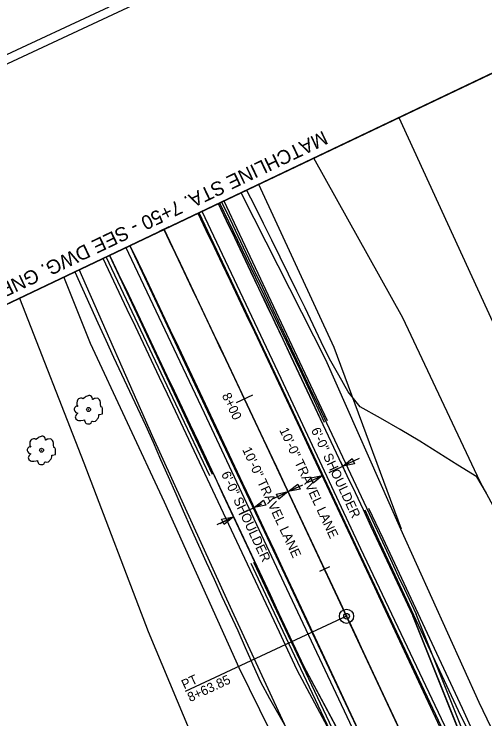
# Model space of a CAD drawing. Extents: x 1040567 to 1041254, y 1126791 to 1127594.
# Drawn here: x 1040797.5 to 1040922.7, y 1127312.2 to 1127499.7 of the extents above; entities that cross this region are included whole.
import ezdxf

# ---------------------------------------------------------------- set-up
doc = ezdxf.new("R2010")
doc.units = 0
for name, color, linetype in [('AC_P', 7, 'Continuous'), ('ACP_P', 7, 'Continuous'), ('ACSC_P_T', 7, 'Continuous'), ('ACSCT_P', 7, 'Continuous'), ('ACSR_P_T', 7, 'Continuous'), ('ACSRT_P', 7, 'Continuous'), ('clip boundary', 7, 'Continuous'), ('LELB', 7, 'Continuous'), ('LFILL_P', 7, 'Continuous'), ('LTD', 7, 'Continuous'), ('NML_P', 7, 'Continuous'), ('NML_P_T', 7, 'Continuous'), ('O_Details_Dimensions_Extension_Lines_P', 7, 'Continuous'), ('PE', 7, 'Continuous'), ('PE_P', 7, 'Continuous'), ('PET_P', 7, 'Continuous'), ('RBS_P', 7, 'Continuous'), ('RDU', 7, 'Continuous'), ('RGB_P', 7, 'Continuous'), ('RGC', 7, 'Continuous'), ('SHEET_BORDER', 7, 'Continuous'), ('STFBY', 7, 'Continuous'), ('STFBY_P', 7, 'Continuous'), ('STSEW', 7, 'Continuous'), ('UEO', 7, 'Continuous')]:
    doc.layers.add(name, color=color, linetype=linetype)

msp = doc.modelspace()

# ---------------------------------------------------------------- linework, layer by layer
at = {"layer": 'AC_P'}
msp.add_line((1040885.87, 1127339.47), (1041008.87, 1127076.16), dxfattribs=at)
msp.add_arc((1027295.55, 1120991.01), 15000, 25.038741, 25.473615, dxfattribs=at)
at = {"layer": 'ACP_P'}
for radius in [1.89, 0.744, 0.154]:
    msp.add_circle((1040885.87, 1127339.47), radius, dxfattribs=at)
at = {"layer": 'ACSCT_P'}
msp.add_lwpolyline([(1040885.87, 1127339.47), (1040842.95, 1127319.43)], dxfattribs=at)
at = {"layer": 'ACSRT_P'}
for points in [[(1040838.6, 1127443.06), (1040836, 1127441.82)], [(1040860.9, 1127398.29), (1040856.56, 1127396.24)], [(1040881.31, 1127352.63), (1040878.7, 1127351.41)]]:
    msp.add_lwpolyline(points, dxfattribs=at)
at = {"layer": 'clip boundary'}
msp.add_lwpolyline([(1040984.84, 1127512.73), (1041214.88, 1127013.05), (1040933.62, 1126879.17), (1040829.04, 1127018.95), (1040710.75, 1127268.88), (1040738.34, 1127281.77), (1040695.57, 1127374.92)], close=True, dxfattribs=at)
at = {"layer": 'LELB'}
for points in [[(1040877.08, 1127461.4), (1040900.78, 1127418.95), (1040921.32, 1127375.3), (1040945.34, 1127330.9), (1040968.92, 1127282.31)], [(1040862.49, 1127454.44), (1040882.5, 1127411.03), (1040900.36, 1127362.7)], [(1040936.75, 1127274.21), (1040940.48, 1127276.28), (1040921.13, 1127316.56), (1040900.31, 1127362.66), (1040880.33, 1127407.66), (1040858.09, 1127451.64), (1040857.81, 1127452.21)], [(1040895.94, 1127263.89), (1040885.7, 1127276.54), (1040878.39, 1127291.15), (1040855.44, 1127340.92), (1040834.33, 1127387.23), (1040814.73, 1127431.69)], [(1040900.67, 1127263.1), (1040889.71, 1127266.18), (1040883.77, 1127274.06), (1040870.94, 1127297.94), (1040857.34, 1127325.72), (1040837.44, 1127369.85), (1040817.74, 1127412), (1040810.73, 1127429.78)], [(1040798.87, 1127424.14), (1040815.97, 1127380.25), (1040833.14, 1127335.38), (1040853.8, 1127286.04), (1040862.66, 1127267.16), (1040867.66, 1127258.25)]]:
    msp.add_lwpolyline(points, dxfattribs=at)
at = {"layer": 'LFILL_P'}
for points in [[(1040923.07, 1127372.19), (1040920.5, 1127376.52), (1040915.46, 1127379.69), (1040910.44, 1127382.88), (1040905.34, 1127386.02), (1040900.15, 1127389.12), (1040894.87, 1127392.17), (1040889.49, 1127395.18), (1040886.26, 1127399.19), (1040883.8, 1127403.57), (1040881.33, 1127407.94), (1040879.14, 1127412.45), (1040876.99, 1127416.97), (1040874.83, 1127421.49), (1040872.65, 1127426), (1040870.45, 1127430.5), (1040868.25, 1127434.99), (1040866.03, 1127439.49), (1040863.81, 1127443.97), (1040861.56, 1127448.45), (1040859.29, 1127452.92)], [(1040813.59, 1127431.15), (1040815.63, 1127426.59), (1040817.68, 1127422.04), (1040819.75, 1127417.5), (1040821.83, 1127412.96), (1040823.92, 1127408.42), (1040826.02, 1127403.9), (1040828.13, 1127399.37), (1040830.25, 1127394.85), (1040832.38, 1127390.34), (1040834.43, 1127385.79), (1040836.42, 1127381.21), (1040838.42, 1127376.63), (1040840.43, 1127372.06), (1040842.45, 1127367.5), (1040844.48, 1127362.94), (1040846.52, 1127358.38), (1040848.57, 1127353.83), (1040850.64, 1127349.29), (1040852.73, 1127344.76), (1040854.86, 1127340.24), (1040856.92, 1127335.7), (1040858.94, 1127331.13), (1040860.5, 1127327.62), (1040860.97, 1127326.57), (1040863.02, 1127322.01), (1040865.38, 1127317.6), (1040867.86, 1127313.23), (1040870.34, 1127308.87)]]:
    msp.add_lwpolyline(points, dxfattribs=at)
at = {"layer": 'LTD'}
for points in [[(1040820.84, 1127395.07), (1040820.57, 1127395.17), (1040820.48, 1127395.3), (1040820.51, 1127395.39), (1040820.45, 1127395.81), (1040820.45, 1127396.37), (1040820.33, 1127396.76), (1040820.18, 1127397.06), (1040819.82, 1127397.43), (1040819.55, 1127397.49), (1040819.02, 1127397.43), (1040818.8, 1127397.37), (1040818.41, 1127397.15), (1040818.35, 1127397.12), (1040818.29, 1127397.34), (1040818.23, 1127397.67), (1040818.02, 1127397.97), (1040817.81, 1127398.12), (1040817.63, 1127398.21), (1040817.38, 1127398.21), (1040817.2, 1127398.12), (1040816.9, 1127398.03), (1040816.66, 1127397.97), (1040816.36, 1127397.79), (1040816.2, 1127397.61), (1040815.77, 1127397.34), (1040815.55, 1127397.52), (1040815.13, 1127397.52), (1040814.62, 1127397.34), (1040814.41, 1127397.18), (1040814.19, 1127396.72), (1040814.13, 1127396.26), (1040814.13, 1127395.84), (1040814.25, 1127395.54), (1040814.41, 1127395.3)], [(1040814.41, 1127395.3), (1040813.95, 1127395.36), (1040813.59, 1127395.05), (1040813.47, 1127394.66), (1040813.47, 1127394.36), (1040813.59, 1127394.06), (1040813.92, 1127393.72), (1040814.16, 1127393.6), (1040814.38, 1127393.54), (1040814.22, 1127393.36), (1040814.1, 1127393.18), (1040813.74, 1127392.53), (1040813.86, 1127391.98), (1040814.31, 1127391.62), (1040814.62, 1127391.59), (1040815.25, 1127391.59), (1040815.8, 1127391.62), (1040816.2, 1127391.74), (1040816.2, 1127391.53), (1040816.36, 1127391.11), (1040816.48, 1127390.9), (1040816.66, 1127390.77), (1040816.99, 1127390.65), (1040817.41, 1127390.62), (1040817.63, 1127390.65), (1040817.93, 1127390.84), (1040818.08, 1127391.23), (1040818.11, 1127391.38), (1040818.29, 1127391.35), (1040818.71, 1127391.29), (1040819.08, 1127391.38), (1040819.2, 1127391.47), (1040819.5, 1127391.77), (1040819.59, 1127391.89), (1040819.82, 1127392.17), (1040819.94, 1127392.35), (1040820.03, 1127392.68), (1040820, 1127393.12), (1040820.21, 1127393.15), (1040820.96, 1127393.31)], [(1040817.31, 1127394.48), (1040817.31, 1127394.48), (1040817.31, 1127394.48), (1040817.31, 1127394.49), (1040817.31, 1127394.49), (1040817.31, 1127394.49), (1040817.31, 1127394.51), (1040817.29, 1127394.51), (1040817.29, 1127394.51), (1040817.29, 1127394.51), (1040817.29, 1127394.51), (1040817.29, 1127394.52), (1040817.28, 1127394.52), (1040817.28, 1127394.52), (1040817.28, 1127394.52), (1040817.26, 1127394.52), (1040817.26, 1127394.52), (1040817.26, 1127394.52), (1040817.25, 1127394.52), (1040817.25, 1127394.52), (1040817.25, 1127394.52), (1040817.23, 1127394.52), (1040817.23, 1127394.51), (1040817.23, 1127394.51), (1040817.23, 1127394.51), (1040817.22, 1127394.51), (1040817.22, 1127394.51), (1040817.22, 1127394.49), (1040817.22, 1127394.49), (1040817.22, 1127394.49), (1040817.22, 1127394.48), (1040817.22, 1127394.48), (1040817.22, 1127394.48), (1040817.22, 1127394.46), (1040817.22, 1127394.46), (1040817.22, 1127394.46), (1040817.22, 1127394.45), (1040817.22, 1127394.45), (1040817.23, 1127394.45), (1040817.23, 1127394.45), (1040817.23, 1127394.43), (1040817.23, 1127394.43), (1040817.25, 1127394.43), (1040817.25, 1127394.43), (1040817.25, 1127394.43), (1040817.26, 1127394.43), (1040817.26, 1127394.43), (1040817.26, 1127394.43), (1040817.28, 1127394.43), (1040817.28, 1127394.43), (1040817.28, 1127394.43), (1040817.29, 1127394.43), (1040817.29, 1127394.43), (1040817.29, 1127394.45), (1040817.29, 1127394.45), (1040817.29, 1127394.45), (1040817.31, 1127394.45), (1040817.31, 1127394.46), (1040817.31, 1127394.46), (1040817.31, 1127394.46), (1040817.31, 1127394.48)], [(1040820.96, 1127393.31), (1040821, 1127393.87), (1040821, 1127394.36), (1040820.94, 1127394.78), (1040820.84, 1127395.07)], [(1040808.33, 1127384.25), (1040808.07, 1127384.35), (1040807.98, 1127384.47), (1040808.01, 1127384.56), (1040807.95, 1127384.98), (1040807.95, 1127385.54), (1040807.83, 1127385.94), (1040807.67, 1127386.24), (1040807.31, 1127386.6), (1040807.04, 1127386.66), (1040806.51, 1127386.6), (1040806.3, 1127386.54), (1040805.91, 1127386.33), (1040805.84, 1127386.3), (1040805.78, 1127386.51), (1040805.72, 1127386.84), (1040805.51, 1127387.15), (1040805.3, 1127387.3), (1040805.12, 1127387.39), (1040804.88, 1127387.39), (1040804.7, 1127387.3), (1040804.39, 1127387.21), (1040804.15, 1127387.15), (1040803.85, 1127386.96), (1040803.7, 1127386.78), (1040803.26, 1127386.51), (1040803.05, 1127386.69), (1040802.62, 1127386.69), (1040802.11, 1127386.51), (1040801.9, 1127386.36), (1040801.69, 1127385.89), (1040801.63, 1127385.44), (1040801.63, 1127385.01), (1040801.75, 1127384.71), (1040801.9, 1127384.47)], [(1040801.9, 1127384.47), (1040801.45, 1127384.53), (1040801.08, 1127384.23), (1040800.96, 1127383.84), (1040800.96, 1127383.53), (1040801.08, 1127383.23), (1040801.42, 1127382.9), (1040801.66, 1127382.78), (1040801.87, 1127382.72), (1040801.72, 1127382.54), (1040801.6, 1127382.35), (1040801.23, 1127381.7), (1040801.35, 1127381.16), (1040801.81, 1127380.8), (1040802.11, 1127380.77), (1040802.75, 1127380.77), (1040803.29, 1127380.8), (1040803.7, 1127380.92), (1040803.7, 1127380.71), (1040803.85, 1127380.28), (1040803.97, 1127380.07), (1040804.15, 1127379.95), (1040804.48, 1127379.83), (1040804.91, 1127379.8), (1040805.12, 1127379.83), (1040805.42, 1127380.01), (1040805.57, 1127380.4), (1040805.6, 1127380.55), (1040805.78, 1127380.52), (1040806.21, 1127380.46), (1040806.57, 1127380.55), (1040806.69, 1127380.65), (1040806.99, 1127380.95), (1040807.08, 1127381.07), (1040807.31, 1127381.34), (1040807.43, 1127381.52), (1040807.52, 1127381.85), (1040807.49, 1127382.29), (1040807.7, 1127382.32), (1040808.45, 1127382.48)], [(1040804.8, 1127383.65), (1040804.8, 1127383.65), (1040804.8, 1127383.65), (1040804.8, 1127383.67), (1040804.8, 1127383.67), (1040804.8, 1127383.67), (1040804.8, 1127383.68), (1040804.79, 1127383.68), (1040804.79, 1127383.68), (1040804.79, 1127383.68), (1040804.79, 1127383.68), (1040804.79, 1127383.7), (1040804.77, 1127383.7), (1040804.77, 1127383.7), (1040804.77, 1127383.7), (1040804.76, 1127383.7), (1040804.76, 1127383.7), (1040804.76, 1127383.7), (1040804.74, 1127383.7), (1040804.74, 1127383.7), (1040804.74, 1127383.7), (1040804.73, 1127383.7), (1040804.73, 1127383.68), (1040804.73, 1127383.68), (1040804.73, 1127383.68), (1040804.71, 1127383.68), (1040804.71, 1127383.68), (1040804.71, 1127383.67), (1040804.71, 1127383.67), (1040804.71, 1127383.67), (1040804.71, 1127383.65), (1040804.71, 1127383.65), (1040804.71, 1127383.65), (1040804.71, 1127383.64), (1040804.71, 1127383.64), (1040804.71, 1127383.64), (1040804.71, 1127383.62), (1040804.71, 1127383.62), (1040804.73, 1127383.62), (1040804.73, 1127383.62), (1040804.73, 1127383.61), (1040804.73, 1127383.61), (1040804.74, 1127383.61), (1040804.74, 1127383.61), (1040804.74, 1127383.61), (1040804.76, 1127383.61), (1040804.76, 1127383.61), (1040804.76, 1127383.61), (1040804.77, 1127383.61), (1040804.77, 1127383.61), (1040804.77, 1127383.61), (1040804.79, 1127383.61), (1040804.79, 1127383.61), (1040804.79, 1127383.62), (1040804.79, 1127383.62), (1040804.79, 1127383.62), (1040804.8, 1127383.62), (1040804.8, 1127383.64), (1040804.8, 1127383.64), (1040804.8, 1127383.64), (1040804.8, 1127383.65)], [(1040808.45, 1127382.48), (1040808.49, 1127383.05), (1040808.49, 1127383.53), (1040808.43, 1127383.96), (1040808.33, 1127384.25)]]:
    msp.add_lwpolyline(points, dxfattribs=at)
for centre in [(1040817.26, 1127394.48), (1040804.76, 1127383.65)]:
    msp.add_circle(centre, 0.533, dxfattribs=at)
at = {"layer": 'NML_P'}
msp.add_line((1040710.81, 1127382.18), (1040984.84, 1127512.73), dxfattribs=at)
at = {"layer": 'O_Details_Dimensions_Extension_Lines_P'}
for p, q in [((1040889.19, 1127381.43), (1040884.84, 1127379.39)), ((1040882.81, 1127378.45), (1040884.84, 1127379.39)), ((1040886.02, 1127376.87), (1040884.31, 1127380.53)), ((1040880.55, 1127374.66), (1040878.97, 1127378.06)), ((1040881.22, 1127377.7), (1040883.26, 1127378.66)), ((1040875.51, 1127375.07), (1040879.49, 1127376.93)), ((1040871.62, 1127369.9), (1040869.82, 1127373.76)), ((1040870.35, 1127372.62), (1040874.26, 1127374.45)), ((1040866.42, 1127370.79), (1040870.38, 1127372.64)), ((1040859.48, 1127367.55), (1040863.37, 1127369.37)), ((1040862.38, 1127366.03), (1040860.75, 1127369.52)), ((1040856.92, 1127363.55), (1040855.28, 1127367.05)), ((1040857.32, 1127366.54), (1040859.48, 1127367.55)), ((1040851.46, 1127363.88), (1040855.81, 1127365.91)), ((1040852.23, 1127364.16), (1040854.13, 1127365.05))]:
    msp.add_line(p, q, dxfattribs=at)
for points in [[(1040887.99, 1127380.04), (1040884.84, 1127379.39), (1040887.36, 1127381.4)], [(1040876.34, 1127376.28), (1040879.49, 1127376.93), (1040876.98, 1127374.92)], [(1040873.53, 1127373.28), (1040870.38, 1127372.64), (1040872.9, 1127374.64)], [(1040867.2, 1127371.98), (1040870.35, 1127372.62), (1040867.83, 1127370.62)], [(1040864.43, 1127369.03), (1040861.28, 1127368.39), (1040863.79, 1127370.39)], [(1040852.66, 1127365.27), (1040855.81, 1127365.91), (1040853.3, 1127363.91)]]:
    msp.add_lwpolyline(points, close=True, dxfattribs=at)
at = {"layer": 'PE'}
for points in [[(1040847.43, 1127447.27), (1040868.4, 1127402.85), (1040889.6, 1127357.48), (1040910.99, 1127312.25), (1040921.84, 1127289.56), (1040927.61, 1127281.92), (1040934.93, 1127267.48)], [(1040907.03, 1127261.18), (1040900.63, 1127274.91), (1040900.82, 1127278.62), (1040899.8, 1127283.28), (1040890.42, 1127303.45), (1040869.29, 1127348.25), (1040848.09, 1127393.47), (1040827.22, 1127437.64)]]:
    msp.add_lwpolyline(points, dxfattribs=at)
at = {"layer": 'PE_P'}
for p, q in [((1040916.89, 1127306.16), (1040903.46, 1127339.62)), ((1040874.47, 1127326.08), (1040891.52, 1127294.31))]:
    msp.add_line(p, q, dxfattribs=at)
for points in [[(1040851.74, 1127449.32), (1040853.89, 1127444.8), (1040856.04, 1127440.28), (1040858.19, 1127435.76), (1040860.34, 1127431.24), (1040862.49, 1127426.72), (1040864.63, 1127422.2), (1040866.77, 1127417.67), (1040868.92, 1127413.15), (1040871.06, 1127408.62), (1040873.19, 1127404.1), (1040875.33, 1127399.57), (1040877.47, 1127395.05), (1040879.6, 1127390.52), (1040881.73, 1127385.99), (1040883.86, 1127381.46), (1040885.99, 1127376.93), (1040888.12, 1127372.4), (1040890.25, 1127367.87), (1040892.37, 1127363.34), (1040894.5, 1127358.8), (1040896.62, 1127354.27), (1040898.74, 1127349.74), (1040900.37, 1127346.25), (1040903.46, 1127339.62)], [(1040822.85, 1127435.56), (1040825, 1127431.05), (1040827.15, 1127426.54), (1040829.29, 1127422.03), (1040831.43, 1127417.52), (1040833.57, 1127413), (1040835.71, 1127408.49), (1040837.85, 1127403.98), (1040839.99, 1127399.46), (1040842.13, 1127394.95), (1040844.26, 1127390.43), (1040846.39, 1127385.92), (1040848.52, 1127381.4), (1040850.65, 1127376.88), (1040852.78, 1127372.36), (1040854.91, 1127367.84), (1040857.03, 1127363.32), (1040859.15, 1127358.8), (1040861.28, 1127354.28), (1040863.4, 1127349.76), (1040865.52, 1127345.23), (1040867.63, 1127340.71), (1040869.75, 1127336.19), (1040871.38, 1127332.7), (1040874.47, 1127326.08)]]:
    msp.add_lwpolyline(points, dxfattribs=at)
at = {"layer": 'PET_P'}
for points in [[(1040846.32, 1127446.74), (1040848.48, 1127442.22), (1040850.63, 1127437.71), (1040852.77, 1127433.19), (1040854.92, 1127428.67), (1040857.07, 1127424.15), (1040859.21, 1127419.63), (1040861.35, 1127415.11), (1040863.49, 1127410.58), (1040865.63, 1127406.06), (1040867.77, 1127401.54), (1040869.9, 1127397.01), (1040872.04, 1127392.49), (1040874.17, 1127387.96), (1040876.3, 1127383.43), (1040878.43, 1127378.91), (1040880.56, 1127374.38), (1040882.69, 1127369.85), (1040884.82, 1127365.32), (1040886.94, 1127360.79), (1040889.06, 1127356.26), (1040891.18, 1127351.73), (1040893.3, 1127347.2), (1040894.93, 1127343.71), (1041018.16, 1127079.92)], [(1040828.27, 1127438.14), (1040830.42, 1127433.63), (1040832.56, 1127429.12), (1040834.71, 1127424.6), (1040836.85, 1127420.09), (1040839, 1127415.58), (1040841.14, 1127411.06), (1040843.28, 1127406.55), (1040845.41, 1127402.03), (1040847.55, 1127397.51), (1040849.68, 1127392.99), (1040851.82, 1127388.48), (1040853.95, 1127383.96), (1040856.08, 1127379.44), (1040858.21, 1127374.92), (1040860.34, 1127370.4), (1040862.46, 1127365.87), (1040864.59, 1127361.35), (1040866.71, 1127356.83), (1040868.83, 1127352.3), (1040870.95, 1127347.78), (1040873.07, 1127343.25), (1040875.18, 1127338.73), (1040876.81, 1127335.24), (1041000.04, 1127071.45)]]:
    msp.add_lwpolyline(points, dxfattribs=at)
at = {"layer": 'RBS_P'}
for p, q in [((1040917.79, 1127306.58), (1040904.37, 1127340.05)), ((1040872.68, 1127325.18), (1040889.73, 1127293.41))]:
    msp.add_line(p, q, dxfattribs=at)
for points in [[(1040852.64, 1127449.75), (1040852.65, 1127449.75), (1040854.8, 1127445.23), (1040856.95, 1127440.71), (1040859.1, 1127436.19), (1040861.25, 1127431.66), (1040863.39, 1127427.14), (1040865.54, 1127422.62), (1040867.68, 1127418.1), (1040869.82, 1127413.57), (1040871.96, 1127409.05), (1040874.1, 1127404.52), (1040876.24, 1127400), (1040878.37, 1127395.47), (1040880.51, 1127390.94), (1040882.64, 1127386.41), (1040884.77, 1127381.88), (1040886.9, 1127377.35), (1040889.03, 1127372.82), (1040891.15, 1127368.29), (1040893.28, 1127363.76), (1040895.4, 1127359.23), (1040897.52, 1127354.69), (1040899.64, 1127350.16), (1040901.28, 1127346.67), (1040904.37, 1127340.05)], [(1040821.05, 1127434.7), (1040823.19, 1127430.19), (1040825.34, 1127425.68), (1040827.48, 1127421.17), (1040829.63, 1127416.66), (1040831.77, 1127412.15), (1040833.91, 1127407.63), (1040836.05, 1127403.12), (1040838.18, 1127398.61), (1040840.32, 1127394.09), (1040842.45, 1127389.58), (1040844.58, 1127385.06), (1040846.71, 1127380.55), (1040848.84, 1127376.03), (1040850.97, 1127371.51), (1040853.1, 1127366.99), (1040855.22, 1127362.47), (1040857.34, 1127357.95), (1040859.47, 1127353.43), (1040861.59, 1127348.91), (1040863.7, 1127344.39), (1040865.82, 1127339.86), (1040867.94, 1127335.34), (1040869.56, 1127331.86), (1040872.68, 1127325.18)]]:
    msp.add_lwpolyline(points, dxfattribs=at)
at = {"layer": 'RDU'}
for points in [[(1040852.12, 1127449.5), (1040873.42, 1127405.13), (1040879.9, 1127391.13)], [(1040850.21, 1127377.19), (1040843.51, 1127391.44), (1040822.8, 1127435.53)], [(1040890.71, 1127367.77), (1040894.38, 1127359.82), (1040915.53, 1127314.36), (1040930.78, 1127283.82)], [(1040897.03, 1127275.98), (1040885.98, 1127301.43), (1040865.01, 1127345.7), (1040861.21, 1127353.79)]]:
    msp.add_lwpolyline(points, dxfattribs=at)
at = {"layer": 'RGB_P'}
for points in [[(1040851.74, 1127449.32), (1040853.88, 1127444.83), (1040856.03, 1127440.31), (1040858.18, 1127435.79), (1040860.33, 1127431.26), (1040862.48, 1127426.74), (1040864.62, 1127422.22), (1040866.77, 1127417.69), (1040868.91, 1127413.17), (1040871.05, 1127408.64), (1040873.19, 1127404.11), (1040875.33, 1127399.58), (1040877.46, 1127395.06), (1040879.6, 1127390.53), (1040881.73, 1127386), (1040883.86, 1127381.47), (1040885.99, 1127376.93), (1040888.12, 1127372.4), (1040890.25, 1127367.87), (1040892.37, 1127363.34), (1040894.5, 1127358.8), (1040896.62, 1127354.27), (1040903.46, 1127339.62), (1040916.89, 1127306.16)], [(1040822.85, 1127435.56), (1040823.1, 1127435.04), (1040825.24, 1127430.53), (1040827.39, 1127426.02), (1040829.53, 1127421.51), (1040831.68, 1127417), (1040833.82, 1127412.49), (1040835.95, 1127407.98), (1040838.09, 1127403.46), (1040840.23, 1127398.95), (1040842.36, 1127394.44), (1040844.5, 1127389.92), (1040846.63, 1127385.41), (1040848.76, 1127380.89), (1040850.89, 1127376.38), (1040853.01, 1127371.86), (1040855.14, 1127367.34), (1040857.26, 1127362.82), (1040859.39, 1127358.3), (1040861.51, 1127353.78), (1040863.63, 1127349.26), (1040865.75, 1127344.74), (1040867.86, 1127340.22), (1040874.47, 1127326.08), (1040891.52, 1127294.31)]]:
    msp.add_lwpolyline(points, dxfattribs=at)
at = {"layer": 'RGC'}
for points in [[(1040853.21, 1127450.02), (1040874.06, 1127405.68), (1040880.74, 1127391.52)], [(1040849.49, 1127376.85), (1040842.82, 1127390.98), (1040821.91, 1127435.11)], [(1040891.73, 1127368.25), (1040895.52, 1127360.22), (1040916.65, 1127315.05), (1040930.78, 1127283.82)], [(1040896.75, 1127275.56), (1040885.31, 1127300.95), (1040864.44, 1127345.17), (1040860.52, 1127353.47)]]:
    msp.add_lwpolyline(points, dxfattribs=at)
at = {"layer": 'SHEET_BORDER'}
msp.add_line((1040772.08, 1127477.98), (1040822.74, 1127501.65), dxfattribs=at)
msp.add_lwpolyline([(1040856.06, 1126819.41), (1040852.74, 1126820.61), (1040588.22, 1127386.88), (1040589.43, 1127390.2), (1040964.86, 1127565.58), (1040968.18, 1127564.37), (1041232.7, 1126998.11), (1041231.49, 1126994.78)], close=True, dxfattribs=at)
at = {"layer": 'STFBY'}
msp.add_lwpolyline([(1040921, 1127264.18), (1040900.77, 1127307.66), (1040879.59, 1127352.84), (1040858.45, 1127397.83), (1040837.33, 1127442.46)], dxfattribs=at)
at = {"layer": 'STFBY_P'}
msp.add_lwpolyline([(1040837.3, 1127442.44), (1040839.45, 1127437.93), (1040841.6, 1127433.41), (1040843.74, 1127428.9), (1040845.89, 1127424.38), (1040848.03, 1127419.86), (1040850.17, 1127415.34), (1040852.31, 1127410.83), (1040854.45, 1127406.31), (1040856.59, 1127401.79), (1040858.73, 1127397.27), (1040860.86, 1127392.74), (1040862.99, 1127388.22), (1040865.13, 1127383.7), (1040867.26, 1127379.18), (1040869.38, 1127374.65), (1040871.51, 1127370.13), (1040873.64, 1127365.6), (1040875.76, 1127361.07), (1040877.88, 1127356.55), (1040880.01, 1127352.02), (1040882.12, 1127347.49), (1040884.24, 1127342.96), (1040885.87, 1127339.47), (1040886.36, 1127338.43), (1040888.48, 1127333.9), (1040890.59, 1127329.37), (1040892.71, 1127324.84), (1040894.82, 1127320.31), (1040896.94, 1127315.78), (1040899.06, 1127311.25)], dxfattribs=at)
at = {"layer": 'STSEW'}
for points in [[(1040846.59, 1127446.87), (1040867.57, 1127402.43), (1040888.89, 1127357.15), (1040910.22, 1127311.85), (1040931.36, 1127266.56)], [(1040910.73, 1127261.79), (1040891.46, 1127303.92), (1040870.37, 1127348.7), (1040849.02, 1127393.89), (1040828.27, 1127438.14)]]:
    msp.add_lwpolyline(points, dxfattribs=at)
at = {"layer": 'UEO'}
msp.add_lwpolyline([(1040899.76, 1127472.2), (1040981.95, 1127293.06)], dxfattribs=at)

# ---------------------------------------------------------------- texts
at = {"layer": 'ACSC_P_T'}
for s, p in [('PT', (1040842.69, 1127319.99)), ('8+63.85', (1040844.28, 1127316.6))]:
    msp.add_text(s, height=2.496, rotation=25.0387, dxfattribs=at).set_placement(p)
at = {"layer": 'ACSR_P_T'}
msp.add_text('8+00', height=2.496, rotation=295.2826, dxfattribs=at).set_placement((1040852.65, 1127398.22))
at = {"layer": 'NML_P_T'}
msp.add_text('MATCHLINE STA. 7+50 - SEE DWG. GNP-02', height=3.744, rotation=205.4736, dxfattribs=at).set_placement((1040879.68, 1127468.73))
at = {"layer": 'O_Details_Dimensions_Extension_Lines_P'}
for s, p in [('10\'-0" TRAVEL LANE', (1040867.94, 1127389.01)), ('6\'-0" SHOULDER', (1040876.36, 1127389.01)), ('10\'-0" TRAVEL LANE', (1040858.07, 1127383.82)), ('6\'-0" SHOULDER', (1040852.47, 1127377.34))]:
    msp.add_text(s, height=2.5008, rotation=295.0387, dxfattribs=at).set_placement(p)

doc.saveas('drawing.dxf')
